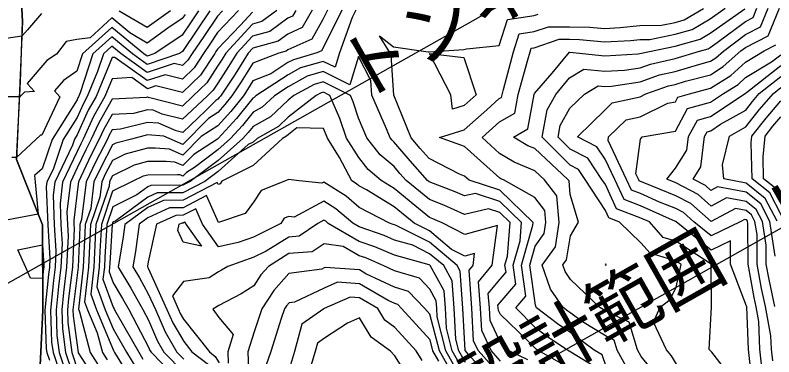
# Model space of a CAD drawing. Extents: x 42655 to 43811, y -141820 to -141156.
# Drawn here: x 42836.1 to 42945.7, y -141729.7 to -141680.3 of the extents above; entities that cross this region are included whole.
import ezdxf

# ---------------------------------------------------------------- set-up
doc = ezdxf.new("R2010")
doc.units = 0
for name, color, linetype in [('D-STR-HTXT', 7, 'Continuous'), ('ZE_HICN', 7, 'Continuous'), ('ZE_LWCN', 7, 'Continuous'), ('地形', 7, 'Continuous'), ('現況道路ﾊｯﾁ', 7, 'Continuous')]:
    doc.layers.add(name, color=color, linetype=linetype)

msp = doc.modelspace()

# ---------------------------------------------------------------- linework, layer by layer
at = {"layer": 'D-STR-HTXT'}
for p, q in [((43148.46, -141542.2), (42816.4, -141729.58)), ((43172.05, -141584), (42839.99, -141771.38))]:
    msp.add_line(p, q, dxfattribs=at)
at = {"layer": 'ZE_HICN'}
for points in [[(42931.69, -141730.79), (42930.94, -141729.59), (42930.22, -141728.7), (42928.37, -141724.73), (42929.33, -141722.55), (42930.75, -141721.46), (42931.63, -141719.65), (42932.36, -141716.37), (42931.62, -141715.89), (42927.87, -141714.76), (42926.52, -141713.25), (42923.44, -141710.25), (42921.91, -141709.65), (42921.41, -141708.58), (42918.49, -141704.11), (42917.51, -141702.64), (42916.29, -141702.01), (42912.27, -141697.97), (42912.99, -141694.02), (42914.23, -141691.8), (42916.23, -141689.42), (42918.29, -141688.13), (42921.31, -141688.46), (42924.17, -141688.29), (42926.4, -141687.95), (42927.91, -141687.41), (42931.48, -141686.62), (42935.01, -141685.54), (42936.27, -141685.19), (42936.56, -141685.02), (42937.56, -141684.32), (42941.63, -141681.26), (42942.74, -141680.69), (42943.3, -141679.34)], [(42864.2, -141679.71), (42862.42, -141682.38), (42860.24, -141685.61), (42859.81, -141685.89), (42855.16, -141687.46), (42853.02, -141685.93), (42850.05, -141683.47), (42847.32, -141685.95), (42845.46, -141691.57), (42845.23, -141692.13), (42845.14, -141692.29), (42845.01, -141692.58), (42841.4, -141698.31), (42839.96, -141702.55), (42838.87, -141703.5), (42838.96, -141704.48), (42839.05, -141705.49), (42839.39, -141709.09), (42835.06, -141709.92)], [(42876.63, -141679.65), (42876.16, -141680.48), (42875.48, -141680.78), (42872.9, -141682.7), (42870.4, -141683.37), (42868.13, -141685.86), (42866.93, -141687.79), (42865.35, -141690.17), (42864.67, -141691.2), (42863.81, -141692.04), (42860.28, -141695.4), (42857.34, -141694.66), (42856.02, -141694.08), (42855.19, -141694.02), (42853.17, -141694.54), (42850.1, -141694.69), (42848.9, -141696.8), (42848.23, -141698.27), (42847, -141700.65), (42845.2, -141704.45), (42845.07, -141705.56), (42844.54, -141709.96), (42844.57, -141710.62), (42844.61, -141711.2), (42844.34, -141716.78), (42843.77, -141721.29), (42843.61, -141722.95), (42843.67, -141724.75), (42844.26, -141729.11), (42845.19, -141731.88)], [(42916.42, -141731.44), (42911.66, -141728.79), (42911.44, -141728.65), (42911.32, -141728.55), (42910.04, -141727.26), (42906.21, -141723.63), (42905.92, -141723.01), (42905.9, -141722.66), (42905.87, -141722.25), (42906.2, -141721.85), (42908.47, -141719.24), (42908.08, -141716.48), (42909.08, -141712.94), (42909.29, -141710.31), (42906.13, -141707.27), (42902.63, -141706.1), (42901.04, -141706.48), (42899.66, -141705.87), (42895.94, -141704.44), (42895.67, -141704.22), (42893.16, -141701.42), (42890.83, -141698.65), (42890.55, -141698.41), (42890.29, -141698.08), (42889.75, -141696.78), (42887.62, -141691.93), (42887.48, -141689.77), (42885.68, -141686.33), (42884.44, -141690.41), (42880.61, -141688.51), (42878.3, -141689.18), (42875.53, -141690.7), (42873.55, -141691.99), (42871.8, -141693.63), (42870.46, -141694.38), (42868.92, -141696.31), (42867.19, -141698.19), (42865.39, -141699.79), (42861.99, -141702.35), (42860.86, -141703.08), (42860.32, -141703.62), (42859.93, -141703.44), (42859.52, -141703.41), (42855.23, -141703.45), (42854.59, -141703.63), (42852.97, -141704.41), (42850.16, -141705.79), (42848.53, -141710.6), (42848.3, -141714.47), (42848.2, -141716.76), (42847.88, -141719.6), (42849.09, -141722.92), (42850.25, -141725.7), (42852.18, -141729.07), (42853.53, -141731.28)], [(42945.9, -141722.47), (42945.06, -141718.53), (42944.65, -141716.31), (42944.64, -141713.61), (42944.09, -141710.15), (42943.19, -141708.42), (42941.75, -141707.27), (42938.91, -141706.74), (42936.67, -141707.93), (42934.81, -141706.28), (42931.56, -141704.57), (42930.28, -141704.05), (42931.55, -141702.48), (42933.18, -141699.86), (42933.43, -141697.88), (42934.69, -141695.54), (42936.61, -141695.01), (42941.59, -141691.68), (42941.65, -141691.64), (42941.68, -141691.61), (42941.79, -141691.54), (42946.75, -141687.64)], [(42901.15, -141730.55), (42900.19, -141728.84), (42899.77, -141727.19), (42899.54, -141722.69), (42899.25, -141718.76), (42898.02, -141716.53), (42895.99, -141714.82), (42893.54, -141713.58), (42890.9, -141712.86), (42889.4, -141712.21), (42885.8, -141710.96), (42884.87, -141710.43), (42882.44, -141708.33), (42880.69, -141707.23), (42876.38, -141709.54), (42875.61, -141709.46), (42874.98, -141709.7), (42874.48, -141710.48), (42870.54, -141712.42), (42868.3, -141713.22), (42865.46, -141713.81), (42863.15, -141710.53), (42862.18, -141708.32), (42860.35, -141709.27), (42859.3, -141709.28), (42856.49, -141710.56), (42855.29, -141716), (42855.21, -141716.62), (42855.19, -141716.73), (42855.23, -141716.8), (42855.3, -141716.91), (42858.01, -141722.88), (42858.84, -141724.79), (42860.43, -141727.51), (42861.62, -141729.02), (42864.02, -141730.85)], [(42840.04, -141718.4), (42838.28, -141718.36), (42837.6, -141716.81), (42836.47, -141714.25), (42840.02, -141713.56), (42840.21, -141716.57), (42840.2, -141716.8), (42840.18, -141716.98), (42840.04, -141718.4)], [(42921.44, -141716.49), (42921.51, -141716.42), (42921.44, -141716.29), (42921.36, -141716.42), (42921.44, -141716.49)], [(42894.92, -141730.25), (42894.06, -141728.87), (42890.95, -141725.48), (42889.53, -141724.45), (42888.5, -141722.74), (42885.85, -141721.2), (42884.48, -141721.1), (42880.76, -141722.74), (42880.7, -141722.77), (42877.5, -141724.99), (42876.43, -141728.96), (42875.72, -141731.34)]]:
    msp.add_lwpolyline(points, dxfattribs=at)
at = {"layer": 'ZE_LWCN'}
for points in [[(42921.51, -141731.14), (42920.92, -141729.46), (42919.78, -141728.75), (42916.4, -141726.26), (42914.46, -141724.96), (42911.45, -141722.63), (42911.38, -141722.53), (42911.29, -141722.28), (42910.48, -141716.47), (42911.25, -141713.72), (42912.55, -141711.88), (42912.81, -141710.3), (42912.66, -141708.56), (42911.22, -141706.72), (42906.66, -141704.16), (42906.26, -141704), (42906.12, -141703.92), (42905.18, -141703.04), (42901.01, -141699.35), (42897.42, -141698.04), (42901, -141696.93), (42904.27, -141694.03), (42906.06, -141692.41), (42906.39, -141692.23), (42906.46, -141691.84), (42906.66, -141691.11), (42908.11, -141685.67), (42908.95, -141683.05), (42911.11, -141682.71), (42913.19, -141682.01), (42916.19, -141682.01), (42919.13, -141682.06), (42921.28, -141682.26), (42923.52, -141682.15), (42926.37, -141681.82), (42929.49, -141681.79), (42931.46, -141681.39), (42932.79, -141681.01), (42935.57, -141679.38)], [(42926.19, -141734.37), (42923.12, -141728.74), (42922.67, -141727.31), (42921.49, -141726.75), (42918.11, -141724.68), (42916.39, -141723.41), (42915.96, -141723.12), (42915.3, -141722.61), (42913.48, -141719.96), (42912.28, -141716.46), (42914.16, -141713.81), (42914.73, -141710.29), (42914.4, -141706.44), (42912.6, -141704.14), (42911.2, -141702.83), (42908.21, -141701.61), (42906.1, -141700.35), (42903.6, -141698.02), (42906.08, -141695.78), (42908.29, -141694.51), (42908.78, -141691.83), (42910.2, -141686.78), (42910.5, -141685.66), (42910.67, -141685.12), (42911.12, -141685.05), (42914.72, -141683.84), (42916.2, -141683.84), (42917.66, -141683.86), (42921.29, -141684.21), (42925.08, -141684.02), (42926.38, -141683.86), (42927.8, -141683.85), (42931.46, -141683.11), (42933.95, -141682.4), (42936.54, -141680.88), (42938.71, -141679.36)], [(42928.72, -141732.31), (42926.59, -141729.7), (42926.06, -141728.72), (42924.81, -141724.7), (42921.47, -141723.13), (42920.59, -141722.59), (42916.36, -141718.54), (42915.58, -141717.39), (42915.25, -141716.45), (42915.76, -141715.73), (42916.33, -141712.22), (42917.53, -141710.28), (42916.31, -141706.25), (42916.14, -141704.31), (42915.99, -141704.12), (42911.19, -141699.64), (42910.16, -141699.22), (42908.1, -141697.99), (42910.19, -141696.79), (42911.1, -141691.82), (42911.15, -141691.66), (42913.68, -141688.72), (42916.21, -141685.71), (42916.25, -141685.68), (42921.3, -141686.23), (42926.08, -141685.96), (42926.39, -141685.91), (42926.6, -141685.84), (42927.77, -141685.58), (42931.47, -141684.82), (42935.11, -141683.8), (42936.55, -141682.95), (42941.54, -141679.45)], [(42939.08, -141732.04), (42936.77, -141729.07), (42936.41, -141728.68), (42936.74, -141722.51), (42936.71, -141716.35), (42931.6, -141713.02), (42929.75, -141712.46), (42927.75, -141710.23), (42926.5, -141709.67), (42923, -141708.32), (42921.39, -141704.84), (42920.9, -141704.1), (42918.84, -141701.01), (42916.28, -141699.69), (42914.56, -141697.96), (42914.86, -141696.27), (42916.25, -141693.79), (42918.39, -141691.78), (42920.33, -141690.57), (42921.32, -141690.68), (42922.26, -141690.63), (42926.41, -141689.99), (42929.23, -141688.99), (42931.49, -141688.49), (42935.03, -141687.41), (42936.57, -141687), (42937.37, -141686.5), (42938.45, -141685.53), (42941.64, -141683.13), (42943.84, -141682.01), (42944.94, -141679.33)], [(42942.64, -141733.88), (42942.07, -141728.65), (42941.84, -141722.51), (42941.84, -141722.49), (42941.83, -141722.47), (42941.82, -141722.41), (42939.5, -141716.34), (42939.49, -141712.95), (42936.7, -141714.29), (42931.64, -141710.21), (42931.61, -141710.18), (42931.59, -141710.17), (42931.54, -141710.15), (42926.49, -141707.9), (42924.1, -141706.98), (42922.76, -141704.09), (42921.37, -141701.18), (42920.17, -141699.38), (42917.38, -141697.95), (42921.34, -141694.01), (42922.37, -141693.02), (42926.42, -141692.15), (42927.23, -141691.74), (42930.54, -141690.57), (42931.5, -141690.36), (42932.99, -141689.9), (42936.58, -141688.96), (42938.44, -141687.78), (42940.97, -141685.52), (42941.65, -141685.01), (42944.94, -141683.33), (42946.58, -141679.33)], [(42839.86, -141680.09), (42837.83, -141682.49), (42837.04, -141683.36), (42833.43, -141683.93)], [(42860.63, -141680.23), (42860.22, -141680.85), (42858.16, -141682.24), (42855.14, -141684.38), (42852.65, -141682.91), (42850.04, -141680.75), (42846.89, -141683.62), (42844.97, -141683.88), (42843.44, -141684.13), (42842.03, -141685.98), (42840.65, -141686.91), (42837.8, -141690.23), (42838.85, -141691.4), (42837.4, -141691.5), (42836.72, -141692.13), (42835.01, -141692.13)], [(42862.59, -141679.72), (42861.53, -141681.31), (42860.23, -141683.23), (42856.25, -141685.91), (42855.15, -141686.28), (42854.65, -141685.92), (42850.05, -141682.11), (42845.82, -141685.96), (42844.99, -141688.46), (42843.04, -141689.77), (42841.76, -141691.27), (42842.53, -141692.14), (42839.94, -141697.68), (42839.71, -141697.69), (42839.05, -141698.32), (42836.28, -141700.9), (42835.58, -141700.9)], [(42866.04, -141679.7), (42865.3, -141680.47), (42863.32, -141683.45), (42861.67, -141685.89), (42861.04, -141686.85), (42860.25, -141687.62), (42859.07, -141687.32), (42855.16, -141688.63), (42851.4, -141685.93), (42850.06, -141684.83), (42848.83, -141685.95), (42847.99, -141688.48), (42846.5, -141692.12), (42845.89, -141693.19), (42845.02, -141695.12), (42843.01, -141698.3), (42841.6, -141702.49), (42840.64, -141704.47), (42840.56, -141705.18), (42840.77, -141710.63), (42841.09, -141715.5), (42841.03, -141716.8), (42840.9, -141717.84), (42840.38, -141722.96), (42840.56, -141728.55), (42840.64, -141729.12), (42841.01, -141730.23)], [(42868.37, -141679.69), (42865.31, -141682.87), (42864.21, -141684.53), (42863.3, -141685.88), (42861.95, -141687.94), (42860.26, -141689.58), (42857.74, -141688.95), (42855.17, -141689.81), (42850.5, -141686.46), (42850.07, -141686.49), (42847.77, -141692.11), (42846.64, -141694.09), (42845.03, -141697.65), (42844.63, -141698.29), (42844.34, -141699.13), (42841.78, -141704.47), (42841.56, -141706.37), (42841.72, -141710.63), (42841.97, -141714.43), (42841.86, -141716.79), (42841.62, -141718.71), (42841.19, -141722.96), (42841.34, -141727.6), (42841.55, -141729.12), (42842.53, -141732.05)], [(42870.39, -141679.91), (42868.66, -141681.8), (42865.33, -141685.27), (42865.1, -141685.6), (42864.92, -141685.87), (42862.85, -141689.03), (42860.27, -141691.54), (42856.42, -141690.57), (42855.18, -141690.99), (42852.92, -141689.37), (42850.08, -141689.56), (42849.04, -141692.11), (42847.4, -141695), (42845.91, -141698.28), (42845.57, -141698.93), (42845.04, -141700.05), (42842.92, -141704.46), (42842.55, -141707.57), (42842.67, -141710.63), (42842.85, -141713.35), (42842.69, -141716.79), (42842.34, -141719.57), (42841.99, -141722.95), (42842.11, -141726.65), (42842.45, -141729.11), (42844.04, -141733.87)], [(42873.89, -141679.67), (42871.72, -141681.28), (42870.4, -141681.64), (42866.53, -141685.86), (42866.01, -141686.69), (42865.34, -141687.71), (42863.76, -141690.12), (42861.77, -141692.05), (42860.27, -141693.48), (42855.32, -141692.25), (42855.23, -141692.21), (42855.18, -141692.21), (42855.05, -141692.24), (42850.09, -141692.48), (42848.15, -141695.9), (42847.07, -141698.28), (42846.29, -141699.79), (42845.05, -141702.39), (42844.06, -141704.46), (42843.55, -141708.76), (42843.62, -141710.62), (42843.73, -141712.28), (42843.51, -141716.78), (42843.06, -141720.43), (42842.8, -141722.95), (42842.89, -141725.7), (42843.36, -141729.11), (42845.2, -141734.63)], [(42878.99, -141679.64), (42877.55, -141682.15), (42875.49, -141683.07), (42874.09, -141684.12), (42870.41, -141685.1), (42869.73, -141685.85), (42867.85, -141688.89), (42865.75, -141692.03), (42865.56, -141692.27), (42865.36, -141692.49), (42865.1, -141692.66), (42863.65, -141694.12), (42860.29, -141697.32), (42859.35, -141697.08), (42856.8, -141695.95), (42855.2, -141695.84), (42851.29, -141696.84), (42850.11, -141696.9), (42849.65, -141697.71), (42849.4, -141698.27), (42847.72, -141701.51), (42846.32, -141704.45), (42845.68, -141709.89), (42845.44, -141710.61), (42845.41, -141711), (42845.16, -141716.78), (42845.12, -141717.16), (42844.49, -141722.15), (42844.41, -141722.94), (42844.44, -141723.8), (42845.17, -141729.1), (42845.18, -141729.13), (42847.4, -141732.58)], [(42881.24, -141679.63), (42880.57, -141680.98), (42878.95, -141683.82), (42875.5, -141685.36), (42875.27, -141685.54), (42874.18, -141685.83), (42870.42, -141687.3), (42868.76, -141689.99), (42867.41, -141692.02), (42866.4, -141693.28), (42865.37, -141694.4), (42864.04, -141695.26), (42860.3, -141699.03), (42857.58, -141697.83), (42855.21, -141697.66), (42852.88, -141698.25), (42850.62, -141698.87), (42850.12, -141699.11), (42848.44, -141702.37), (42847.45, -141704.44), (42847, -141708.28), (42846.21, -141710.61), (42846.14, -141711.87), (42845.92, -141716.77), (42845.23, -141722.84), (42845.26, -141722.94), (42845.38, -141723.22), (42846.91, -141729.09), (42848.38, -141731.38)], [(42883.27, -141679.62), (42880.59, -141685.06), (42880.34, -141685.5), (42879.66, -141685.8), (42876.3, -141686.78), (42875.51, -141687.21), (42873.04, -141688.84), (42870.43, -141689.86), (42869.68, -141691.09), (42869.06, -141692.01), (42867.24, -141694.29), (42865.38, -141696.32), (42862.98, -141697.87), (42860.31, -141700.56), (42858.37, -141699.7), (42856.3, -141699.55), (42855.22, -141699.56), (42851.95, -141700.45), (42850.13, -141701.34), (42849.15, -141703.23), (42848.58, -141704.43), (42848.32, -141706.67), (42846.98, -141710.61), (42846.86, -141712.74), (42846.68, -141716.77), (42846.11, -141721.76), (42846.54, -141722.93), (42847.94, -141726.28), (42848.67, -141729.09), (42849.37, -141730.17)], [(42885.31, -141679.61), (42884.78, -141680.67), (42882.96, -141685.79), (42882.33, -141687.88), (42880.6, -141687.02), (42877.3, -141687.98), (42875.52, -141688.95), (42870.87, -141692.01), (42870.63, -141692.23), (42870.45, -141692.34), (42868.08, -141695.3), (42865.42, -141698.19), (42865.39, -141698.23), (42865.32, -141698.28), (42861.92, -141700.47), (42860.32, -141702.09), (42859.15, -141701.57), (42857.91, -141701.48), (42855.22, -141701.51), (42853.27, -141702.04), (42850.15, -141703.56), (42849.87, -141704.09), (42849.71, -141704.43), (42849.64, -141705.06), (42847.75, -141710.6), (42847.58, -141713.6), (42847.44, -141716.77), (42846.99, -141720.68), (42847.81, -141722.93), (42850.26, -141728.8), (42850.42, -141729.08), (42852.53, -141732.51)], [(42858.53, -141679.74), (42855.13, -141682.14), (42851.09, -141679.77)], [(42919.62, -141731.04), (42916.41, -141729.06), (42915.9, -141728.77), (42912.95, -141726.8), (42911.31, -141725.53), (42908.45, -141722.64), (42909.91, -141720.97), (42909.28, -141716.48), (42910.91, -141710.71), (42910.94, -141710.31), (42906.13, -141705.66), (42901.7, -141704.19), (42901.03, -141703.6), (42900.32, -141703.34), (42895.93, -141701.06), (42894.63, -141699.62), (42893.33, -141698.06), (42890.8, -141691.91), (42890.44, -141686.15), (42890.24, -141685.75), (42888.76, -141683.34), (42890.77, -141684.93), (42895.79, -141685.64), (42895.86, -141685.65), (42895.91, -141685.66), (42900.94, -141685.33), (42901.34, -141685.22), (42906.03, -141684.72), (42907.23, -141680.98), (42911.1, -141680.38), (42911.67, -141680.19)], [(42944.11, -141732.09), (42943.73, -141728.64), (42943.58, -141724.6), (42943.19, -141722.48), (42942.91, -141721.16), (42942.03, -141716.32), (42942, -141710.45), (42941.96, -141710.16), (42941.88, -141710.02), (42941.77, -141709.92), (42941.53, -141709.88), (42940.99, -141710.17), (42936.69, -141712.24), (42934.16, -141710.2), (42932.68, -141708.88), (42931.58, -141708.31), (42929.21, -141707.35), (42926.48, -141706.14), (42925.19, -141705.64), (42924.47, -141704.08), (42921.8, -141698.46), (42921.86, -141697.93), (42924.42, -141695.48), (42926.43, -141695.04), (42930.42, -141693.05), (42931.51, -141692.87), (42931.88, -141692.18), (42933.55, -141691.71), (42936.59, -141690.92), (42939.51, -141689.07), (42941.66, -141687.14), (42944.36, -141685.5), (42946.04, -141684.65)], [(42899.3, -141693.91), (42899.04, -141691.87), (42895.97, -141685.87), (42900.95, -141686.46), (42902.71, -141691.86), (42900.98, -141693.39), (42899.3, -141693.91)], [(42945.58, -141730.29), (42945.39, -141728.63), (42945.32, -141726.68), (42944.54, -141722.47), (42943.98, -141719.85), (42943.34, -141716.32), (42943.32, -141712.03), (42943.02, -141710.16), (42942.54, -141709.22), (42941.76, -141708.6), (42940.22, -141708.31), (42936.68, -141710.19), (42933.74, -141707.58), (42931.57, -141706.44), (42926.87, -141704.55), (42926.47, -141704.37), (42926.29, -141704.3), (42926.18, -141704.07), (42925.79, -141703.26), (42926.45, -141698.25), (42926.71, -141697.91), (42931.53, -141697.12), (42933.28, -141693.86), (42936.6, -141692.94), (42938.46, -141691.69), (42940.58, -141690.35), (42941.67, -141689.38), (42945.43, -141687.09), (42946.74, -141686.06)], [(42945.96, -141715.19), (42945.15, -141710.15), (42943.85, -141707.62), (42941.75, -141705.95), (42937.6, -141705.17), (42936.66, -141705.67), (42935.87, -141704.97), (42934.09, -141704.04), (42935.18, -141702.27), (42935.74, -141697.87), (42936.09, -141697.22), (42936.62, -141697.08), (42938.04, -141696.12), (42941.69, -141694.06), (42942.64, -141692.83), (42943.65, -141691.67), (42946.76, -141689.23)], [(42910.2, -141730.17), (42907.39, -141728.81), (42906.23, -141727.71), (42904.72, -141724.47), (42904.63, -141722.66), (42904.47, -141720.57), (42906.19, -141718.48), (42907.03, -141717.51), (42906.88, -141716.49), (42907.26, -141715.17), (42907.64, -141710.32), (42906.14, -141708.88), (42904.48, -141708.33), (42901.05, -141709.15), (42898.06, -141707.82), (42895.96, -141707.01), (42892.58, -141704.23), (42891.68, -141703.23), (42890.85, -141702.23), (42888.82, -141700.53), (42886.92, -141698.09), (42885.72, -141695.22), (42884.93, -141692.89), (42884.53, -141691.94), (42880.61, -141690), (42879.3, -141690.38), (42876.37, -141691.98), (42875.54, -141692.63), (42872.97, -141695.03), (42870.47, -141696.43), (42869.76, -141697.31), (42868.97, -141698.18), (42865.4, -141701.35), (42861.38, -141704.38), (42860.33, -141704.92), (42855.7, -141704.96), (42855.24, -141705.16), (42853.67, -141706.32), (42850.17, -141708.04), (42849.3, -141710.59), (42849.02, -141715.33), (42848.96, -141716.76), (42848.76, -141718.52), (42850.23, -141722.56), (42850.36, -141722.77), (42850.44, -141722.91), (42850.8, -141723.59), (42853.93, -141729.06), (42854.54, -141730.05)], [(42906.24, -141730.34), (42904.86, -141728.82), (42903.52, -141725.94), (42903.36, -141722.67), (42903.07, -141718.9), (42905.04, -141716.5), (42905.82, -141710.74), (42901.07, -141712.07), (42897.81, -141710.37), (42896.47, -141709.77), (42895.97, -141709.58), (42893.86, -141707.84), (42890.86, -141705.41), (42888.99, -141704.25), (42887.08, -141702.65), (42885.75, -141700.94), (42883.95, -141698.11), (42882.99, -141695.27), (42881.57, -141691.96), (42880.62, -141691.48), (42880.3, -141691.58), (42879.59, -141691.96), (42875.55, -141695.11), (42874.14, -141696.44), (42871.03, -141698.17), (42870.48, -141698.68), (42869.76, -141699.04), (42865.41, -141702.92), (42863.48, -141704.37), (42860.33, -141706.01), (42856.6, -141706.04), (42855.25, -141706.65), (42850.61, -141710.07), (42850.18, -141710.28), (42850.07, -141710.59), (42849.74, -141716.2), (42849.72, -141716.75), (42849.64, -141717.44), (42850.22, -141719.02), (42851.58, -141721.28), (42852.48, -141722.9), (42855.35, -141728.31), (42855.56, -141728.8), (42855.71, -141729.05), (42860.46, -141733.92)], [(42946.22, -141710.14), (42944.5, -141706.82), (42941.74, -141704.62), (42938.51, -141704.01), (42938.34, -141701.96), (42939.34, -141697.85), (42941.7, -141696.51), (42943.63, -141694.02), (42945.69, -141691.66), (42946.76, -141690.81)], [(42946.85, -141709.3), (42945.16, -141706.02), (42942.61, -141704), (42942.49, -141698.78), (42942.59, -141697.83), (42944.63, -141695.21), (42946.77, -141692.74)], [(42945.81, -141705.22), (42944.27, -141703.99), (42944.19, -141700.81), (42944.51, -141697.82), (42945.62, -141696.4), (42946.78, -141695.06)], [(42906.25, -141732.43), (42902.99, -141728.83), (42902.32, -141727.4), (42902.08, -141722.67), (42901.68, -141717.22), (42902.26, -141716.51), (42902.49, -141714.81), (42901.08, -141715.2), (42899.15, -141714.19), (42895.98, -141711.52), (42893.74, -141710.39), (42890.87, -141708.06), (42886.86, -141705.58), (42885.77, -141705.01), (42885.41, -141704.7), (42884.72, -141704.27), (42882.98, -141700.91), (42881.2, -141698.12), (42881.04, -141697.65), (42880.64, -141696.72), (42876.8, -141696.63), (42875.56, -141697.6), (42875.3, -141697.84), (42874.74, -141698.15), (42870.49, -141702.06), (42865.96, -141704.35), (42865.7, -141704.7), (42865.42, -141704.8), (42865.29, -141704.51), (42860.34, -141707.1), (42857.5, -141707.12), (42855.26, -141708.14), (42851.94, -141710.58), (42851.69, -141712.4), (42850.97, -141716.75), (42852.8, -141719.78), (42854.53, -141722.9), (42855.33, -141724.41), (42856.65, -141727.46), (42857.58, -141729.04), (42860.45, -141731.99)], [(42906.26, -141734.52), (42901.57, -141729.35), (42901.15, -141728.87), (42901.13, -141728.84), (42901.12, -141728.81), (42900.81, -141722.68), (42900.41, -141717.34), (42899.96, -141716.52), (42895.99, -141713.17), (42891.17, -141710.74), (42890.89, -141710.66), (42890.73, -141710.59), (42890.17, -141710.4), (42885.78, -141708.12), (42883.93, -141706.51), (42880.68, -141704.48), (42880.4, -141704.63), (42877.12, -141704.3), (42875.59, -141704.08), (42875.17, -141704.31), (42871.61, -141705.67), (42870.52, -141707.37), (42869.31, -141709.03), (42865.44, -141710.3), (42863.73, -141706.41), (42860.34, -141708.18), (42858.4, -141708.2), (42855.26, -141709.63), (42853.98, -141710.57), (42853.45, -141714.51), (42853.08, -141716.74), (42854.02, -141718.29), (42855.31, -141720.63), (42856.34, -141722.89), (42857.75, -141726.13), (42859.45, -141729.03), (42860.45, -141730.05)], [(42901.16, -141732.22), (42899.26, -141728.85), (42898.42, -141725.57), (42898.28, -141722.69), (42898.09, -141720.18), (42896.08, -141716.54), (42896, -141716.47), (42895.91, -141716.43), (42890.91, -141715.05), (42888.08, -141713.82), (42885.81, -141713.04), (42881.31, -141710.44), (42880.96, -141710.14), (42880.71, -141709.98), (42879.82, -141710.45), (42877.14, -141712.3), (42875.63, -141712.41), (42872.37, -141714.45), (42870.55, -141715.34), (42866.81, -141716.68), (42865.92, -141717.22), (42865.48, -141717.46), (42864.12, -141718.33), (42860.39, -141718.82), (42858.79, -141720.92), (42859.68, -141722.87), (42859.93, -141723.46), (42860.42, -141724.29), (42864.14, -141729.01), (42864.99, -141729.66), (42865.54, -141730.58)], [(42859.59, -141711.48), (42859.79, -141710.55), (42860.2, -141710.36), (42860.35, -141710.36), (42860.62, -141710.22), (42860.76, -141710.54), (42862.99, -141713.71), (42860.37, -141713.16), (42859.59, -141711.48)], [(42901.17, -141733.9), (42898.33, -141728.85), (42897.07, -141723.95), (42897.01, -141722.7), (42896.93, -141721.61), (42896.02, -141719.96), (42894.51, -141718.37), (42890.92, -141717.3), (42889.37, -141716.57), (42886.76, -141715.44), (42885.82, -141715.11), (42883.47, -141713.76), (42880.72, -141713.39), (42879.02, -141714.56), (42875.64, -141714.81), (42872.7, -141716.65), (42871.58, -141717.89), (42870.57, -141719.48), (42868.75, -141720.62), (42865.5, -141722.31), (42864.66, -141722.85), (42865.51, -141724.05), (42867.6, -141726.48), (42866.83, -141729), (42866.88, -141730.63)], [(42900.19, -141733.82), (42897.39, -141728.86), (42896.03, -141723.56), (42895.26, -141722.71), (42892.95, -141720.27), (42890.93, -141719.67), (42886.76, -141717.71), (42885.83, -141717.17), (42880.9, -141716.8), (42880.74, -141716.87), (42880.38, -141717.04), (42875.65, -141717.66), (42873.44, -141720.12), (42871.74, -141722.81), (42870.6, -141726.09), (42869.72, -141728.99), (42869.89, -141734.24)], [(42897.3, -141730.36), (42896.46, -141728.86), (42896.05, -141727.27), (42891.91, -141722.72), (42891.39, -141722.17), (42890.94, -141722.04), (42890, -141721.6), (42885.84, -141719.18), (42882.69, -141718.95), (42880.75, -141719.81), (42876.46, -141721.84), (42875.67, -141721.94), (42875.3, -141722.35), (42875.02, -141722.8), (42874.54, -141724.19), (42873.04, -141728.97), (42872.32, -141731.03)], [(42892.93, -141732.69), (42890.97, -141729.57), (42890.33, -141728.89), (42887.55, -141726.87), (42885.86, -141724.07), (42884.12, -141724.87), (42880.78, -141727.04), (42879.79, -141727.73), (42879.46, -141728.94), (42878.69, -141731.5)]]:
    msp.add_lwpolyline(points, dxfattribs=at)
at = {"layer": '地形'}
msp.add_lwpolyline([(42830.26, -141803.12), (42840.48, -141800.86), (42847.21, -141794.4), (42855.64, -141787.38), (42858.16, -141779.52), (42855.07, -141769.98), (42850.44, -141766.05), (42845.25, -141762.12), (42844.13, -141756.78), (42840.17, -141747.61), (42839.35, -141737.97), (42840.06, -141722.96), (42840, -141710.64), (42836.27, -141701.2), (42836.83, -141689.97), (42837.11, -141681.27), (42836.55, -141669.76), (42834.68, -141661.36)], dxfattribs=at)
at = {"layer": '現況道路ﾊｯﾁ'}
msp.add_lwpolyline([(42834.68, -141661.36), (42836.55, -141669.76), (42837.11, -141681.27), (42836.27, -141701.2), (42840, -141710.64), (42840.06, -141722.96), (42839.35, -141737.97), (42840.17, -141747.61), (42844.13, -141756.78), (42845.25, -141762.12), (42850.44, -141766.05), (42855.07, -141769.98), (42858.16, -141779.52), (42855.64, -141787.38), (42847.21, -141794.4), (42840.48, -141800.86), (42830.26, -141803.12)], dxfattribs=at)

# ---------------------------------------------------------------- texts
at = {"layer": 'D-STR-HTXT'}
for s, p in [('トンネル工\u3000L=748.0m', (42885.63, -141693.02)), ('設計範囲\u3000L=1.25km', (42903.35, -141738.36))]:
    msp.add_text(s, height=7.9662, rotation=29.5191, dxfattribs=at).set_placement(p)

doc.saveas('drawing.dxf')
